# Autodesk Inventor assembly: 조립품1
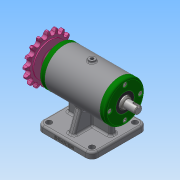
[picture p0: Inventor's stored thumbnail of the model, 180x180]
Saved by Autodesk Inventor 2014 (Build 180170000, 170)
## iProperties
Created: 2019-06
Part Number: 조립품1
Document SubType Name: Assembly
Designer: net
Author: net
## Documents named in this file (9)
- C:\Users\net\Desktop\490604V1028\답안조립품.iam
- C:\Users\net\Desktop\490604V1028\본체.ipt
- C:\Users\net\Desktop\490604V1028\커버.ipt
- C:\Users\net\Desktop\490604V1028\베어링 6203.ipt
- C:\Users\net\Desktop\490604V1028\볼트 M4.ipt
- C:\Users\net\Desktop\490604V1028\축.ipt
- C:\Users\net\Desktop\490604V1028\키 4x4x12.ipt
- C:\Users\net\Desktop\490604V1028\오일 실 17 30 5.ipt
- C:\Users\net\Desktop\490604V1028\스프로킷.ipt
